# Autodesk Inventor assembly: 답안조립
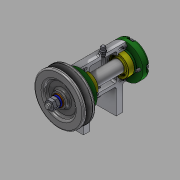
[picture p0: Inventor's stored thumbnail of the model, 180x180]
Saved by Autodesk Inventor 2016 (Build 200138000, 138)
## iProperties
Created: 2018-05
Part Number: 답안조립
Material: 일반
Document SubType Name: Assembly
Designer: Administrator
Author: Administrator
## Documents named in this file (16)
- C:\Users\Administrator\Desktop\480507V1013\답안조립.iam
- C:\Users\Administrator\Desktop\480507V1013\본체.ipt
- C:\Users\Administrator\Desktop\480507V1013\축.ipt
- C:\Users\Administrator\Desktop\480507V1013\베어링 6002.ipt
- C:\Users\Administrator\Desktop\480507V1013\뒤커버.ipt
- C:\Users\Administrator\Desktop\480507V1013\앞커버.ipt
- C:\Users\Administrator\Desktop\480507V1013\오일 실 15 25 7.ipt
- C:\Users\Administrator\Desktop\480507V1013\V벨트풀리.ipt
- C:\Users\Administrator\Desktop\480507V1013\키 3x3x12.ipt
- C:\Users\Administrator\Desktop\480507V1013\와셔 8x17.ipt
- C:\Users\Administrator\Desktop\480507V1013\스프링와셔 8.ipt
- C:\Users\Administrator\Desktop\480507V1013\너트 M8.ipt
- C:\Users\Administrator\Desktop\480507V1013\볼트 M4x12.ipt
- C:\Users\Administrator\Desktop\480507V1013\니플 M6x0.75.ipt
- C:\Users\Administrator\Desktop\480507V1013\와셔 6x11.5.ipt
- C:\Users\Administrator\Desktop\480507V1013\볼트 M6x8.ipt
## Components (1 placed, 1 different names)
1. V벨트풀리:1
